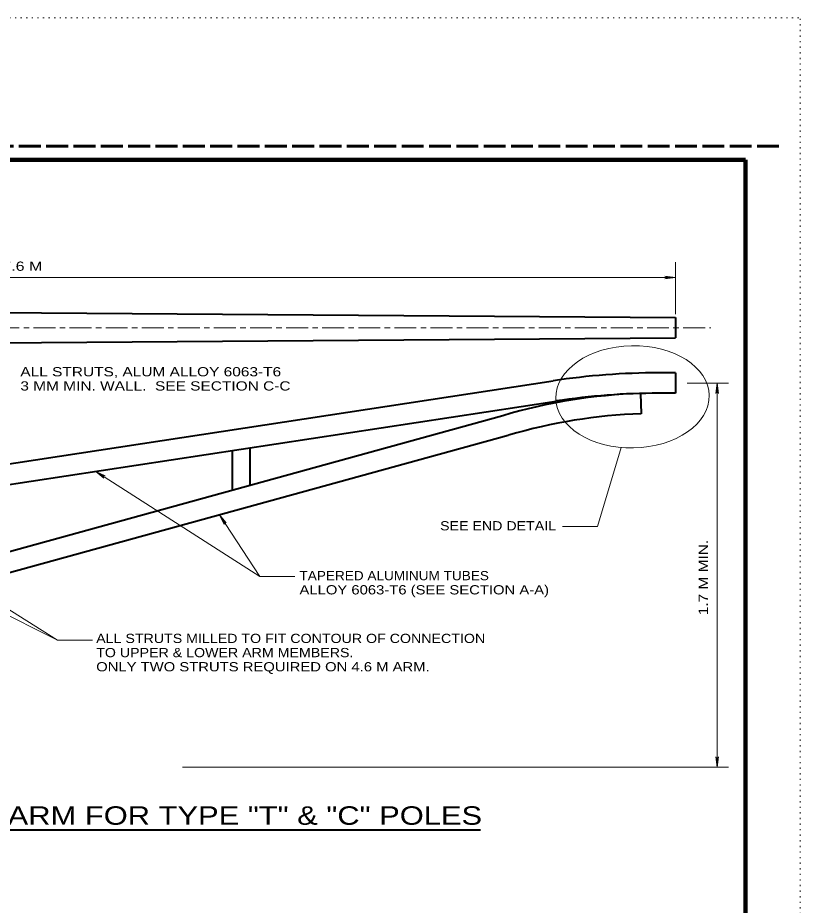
# Model space of a CAD drawing. Extents: x 312583 to 312854, y 144419 to 144597.
# Drawn here: x 312789.1 to 312853.5, y 144523.7 to 144596.8 of the extents above; entities that cross this region are included whole.
import ezdxf
from ezdxf.enums import TextEntityAlignment as Align

# ---------------------------------------------------------------- set-up
doc = ezdxf.new("R2010")
doc.units = 0
doc.header["$LTSCALE"] = 0.3
for name, pattern in [('DOTTED', [1.5, 0.3, -1.2]), ('LONG_DASH_SHORT_DASH', [9.9, 6, -1.2, 1.5, -1.2]), ('LONG_DASHED', [7.5, 6, -1.5])]:
    doc.linetypes.add(name, pattern=pattern)
for name, color, linetype, lineweight in [('1', 7, 'Continuous', 40), ('62', 7, 'DOTTED', 13), ('63', 7, 'LONG_DASHED', 60)]:
    doc.layers.add(name, color=color, linetype=linetype, lineweight=lineweight)

msp = doc.modelspace()

# ---------------------------------------------------------------- linework, layer by layer
at = {"layer": '1', "lineweight": 158}
msp.add_line((312849, 144423.1446), (312849, 144585.0846), dxfattribs=at)
at = {"layer": '1', "lineweight": 13}
for p, q in [((312843.2319, 144572.3975), (312843.2319, 144576.6609)), ((312728.2319, 144575.4042), (312843.2319, 144575.4042)), ((312842.3655, 144575.5115), (312842.6415, 144575.4042)), ((312843.2319, 144575.4042), (312842.3655, 144575.5115)), ((312842.3655, 144575.2969), (312842.6415, 144575.4042)), ((312843.2319, 144575.4042), (312842.3655, 144575.2969)), ((312844.1902, 144566.7165), (312847.5868, 144566.7165)), ((312846.6641, 144566.7165), (312846.5568, 144565.8502)), ((312846.6641, 144566.7165), (312846.6641, 144535.0915)), ((312846.6641, 144566.7165), (312846.7714, 144565.8502)), ((312846.5568, 144565.8502), (312846.6641, 144566.1262)), ((312846.7714, 144565.8502), (312846.6641, 144566.1262)), ((312809.0309, 144550.7928), (312795.5299, 144559.4485)), ((312795.5299, 144559.4485), (312796.1969, 144558.8888)), ((312795.5299, 144559.4485), (312796.3119, 144559.0728)), ((312796.1969, 144558.8888), (312796.0282, 144559.1265)), ((312796.3119, 144559.0728), (312796.0282, 144559.1265)), ((312809.0309, 144550.7928), (312805.6959, 144555.8682)), ((312805.6959, 144555.8682), (312806.0869, 144555.0862)), ((312805.6959, 144555.8682), (312806.2632, 144555.2012)), ((312806.0869, 144555.0862), (312806.0255, 144555.3775)), ((312806.2632, 144555.2012), (312806.0255, 144555.3775)), ((312809.0309, 144550.7928), (312811.9135, 144550.7928)), ((312792.3789, 144545.5642), (312795.2539, 144545.5642)), ((312846.5568, 144535.9578), (312846.6641, 144535.6818)), ((312846.6641, 144535.0915), (312846.5568, 144535.9578)), ((312846.7714, 144535.9578), (312846.6641, 144535.6818)), ((312846.6641, 144535.0915), (312846.7714, 144535.9578)), ((312802.6522, 144535.0915), (312847.5868, 144535.0915))]:
    msp.add_line(p, q, dxfattribs=at)
at = {"layer": '1'}
for p, q in [((312729.8495, 144572.9342), (312843.2319, 144572.1062)), ((312843.2319, 144572.1062), (312843.2319, 144570.4348)), ((312729.8495, 144569.6068), (312843.2319, 144570.4348)), ((312843.2319, 144567.5598), (312841.8519, 144567.5598)), ((312843.2319, 144567.5598), (312843.2319, 144565.8808)), ((312729.8495, 144551.1072), (312833.1655, 144566.9005)), ((312840.3569, 144565.8578), (312840.4105, 144564.1865)), ((312843.2319, 144565.8808), (312841.8519, 144565.8808)), ((312729.8495, 144549.4052), (312833.4185, 144565.2368)), ((312729.8495, 144536.7322), (312829.0255, 144564.0332)), ((312729.8649, 144534.9918), (312829.4702, 144562.4155)), ((312808.1952, 144561.3805), (312808.1952, 144558.2985)), ((312806.7539, 144561.1658), (312806.7539, 144557.8998)), ((312759.5774, 144529.9318), (312827.1878, 144529.9318))]:
    msp.add_line(p, q, dxfattribs=at)
at = {"layer": '1', "linetype": 'LONG_DASH_SHORT_DASH', "lineweight": 13}
msp.add_line((312725.0655, 144571.2705), (312846.1375, 144571.2705), dxfattribs=at)
at = {"layer": '1', "lineweight": 158}
msp.add_lwpolyline([(312616.5, 144423.1446), (312616.5, 144585.0846), (312849, 144585.0846)], dxfattribs=at)
at = {"layer": '1', "lineweight": 13}
for points in [[(312833.9399, 144554.9022), (312836.8149, 144554.9022), (312838.7545, 144561.4112)], [(312780.8789, 144557.2098), (312778.9775, 144553.9822), (312792.3789, 144545.5642), (312781.6609, 144550.9232)]]:
    msp.add_lwpolyline(points, dxfattribs=at)
at = {"layer": '1'}
for centre, radius, start, end in [((312841.8544, 144510.0574), 57.5, 90, 98.69133), ((312841.8105, 144520.8729), 45.0108, 91.84829, 106.4991), ((312841.8544, 144510.0574), 55.8229, 90, 98.69133), ((312841.8105, 144520.8729), 43.3337, 91.84829, 106.4991)]:
    msp.add_arc(centre, radius, start, end, dxfattribs=at)
at = {"layer": '1', "lineweight": 13}
msp.add_ellipse((312839.6993, 144565.5824), major_axis=(-6.3127, -0.1234), ratio=0.666667, dxfattribs=at)
at = {"layer": '62'}
msp.add_line((312601.2, 144596.7846), (312853.5, 144596.7846), dxfattribs=at)
msp.add_lwpolyline([(312601.2, 144418.5846), (312853.5, 144418.5846), (312853.5, 144596.7846)], dxfattribs=at)
at = {"layer": '63'}
msp.add_line((312851.75, 144586.2246), (312583.526, 144586.2246), dxfattribs=at)

# ---------------------------------------------------------------- texts
at = {"layer": '1'}
for s, width, p in [('4.6 M, 6.1 M, OR 7.6 M', 1.3, (312777.4063, 144575.9553)), ('ALL STRUTS, ALUM ALLOY 6063-T6', 1.25, (312789.3199, 144567.2675)), ('3 MM MIN. WALL.  SEE SECTION C-C', 1.25, (312789.3199, 144566.1012)), ('SEE END DETAIL', 1.15, (312823.8607, 144554.5888)), ('TAPERED ALUMINUM TUBES', 1.1, (312812.2892, 144550.4852)), ('ALLOY 6063-T6 (SEE SECTION A-A)', 1.2, (312812.2892, 144549.3189)), ('ALL STRUTS MILLED TO FIT CONTOUR OF CONNECTION', 1.15, (312795.5605, 144545.3178)), ('TO UPPER & LOWER ARM MEMBERS.', 1.15, (312795.5605, 144544.1515)), ('ONLY TWO STRUTS REQUIRED ON 4.6 M ARM.', 1.2, (312795.5605, 144542.9852))]:
    msp.add_text(s, height=0.76, dxfattribs=dict(at, width=width)).set_placement(p)
at = {"layer": '1', "width": 1.25}
msp.add_text('1.7 M MIN.', height=0.76, rotation=90, dxfattribs=at).set_placement((312845.9011, 144547.6042))
msp.add_text('TRAFFIC SIGNAL MAST ARM FOR TYPE "T" & "C" POLES', height=1.52, dxfattribs=at).set_placement((312793.1876, 144530.3583), align=Align.CENTER)

doc.saveas('drawing.dxf')
